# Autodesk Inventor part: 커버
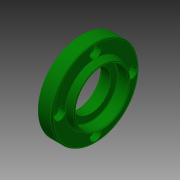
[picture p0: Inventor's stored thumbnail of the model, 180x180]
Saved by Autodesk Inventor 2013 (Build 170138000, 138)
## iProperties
Created: 2018-11
Part Number: 커버
Material: 알루미늄 6061
Document SubType Name: Modeling
Designer: mduedu
Density: 1 g/cm^3
Author: mduedu
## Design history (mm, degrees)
revolve "회전1" stored, may be unused: angle "d7" = 90 deg
sketch "스케치2"
  geometry: L1 (0, -20)-(0, 20) reference; L2 (0, 20)-(3, 20) reference; L3 (3, 20)-(3, 31) reference; L4 (3, 31)-(13, 31) reference; L5 (13, 31)-(13, 21.5) reference; L6 (18, 20)-(18, -20) reference; L7 (13, -21.5)-(13, -31) reference; L8 (13, -31)-(3, -31) reference; L9 (3, -31)-(3, -20) reference; L10 (3, -20)-(0, -20) reference; L11 (0, 0)-(3, 0); L12 (3, 0)-(3, 16.5); L13 (3, 16.5)-(0, 16.5); L14 (0, 16.5)-(0, 0); L15 (3, 0)-(9.7, 0); L16 (9.7, 0)-(9.7, 14); L17 (9.7, 14)-(3, 14); L18 (3, 14)-(3, 0); L19 (9.7, 0)-(18, 0); L20 (18, 0)-(18, 19); L21 (18, 19)-(9.7, 19); L22 (9.7, 19)-(9.7, 0); L23 (13, 21.5)-(18, 20) reference; L24 (18, -20)-(13, -21.5) reference
  constraints: 24 end point, 6 parallel, 3 horizontal, 3 perpendicular, 1 point on line
  dimensions: "d8" = 38 diameter of L21 L19; "d10" = 28 diameter of L17 L15; "d11" = 33 diameter of L13 L11; "d12" = 3 distance of L12.end L13.end; "d13" = 8.3 distance of L20.end L21.end
revolve "회전2" sketch "스케치2" stored, may be unused: angle "d14" = 90 deg
fillet "모깎기1" dims "d15" = 0.3
chamfer "모따기1" distance "d16" = 0.8; stored, may be unused: second distance "d17" = 2, angle "d18" = 30 deg
fillet "모깎기2" dims "d19" = 1
chamfer "모따기2" distance "d20" = 0.5; stored, may be unused: second distance "d21" = 2, angle "d22" = 30 deg
sketch "스케치3" dims "d23" = 52
  geometry: 6 further points
  constraints: 2 vertical alignment, 1 coincident, 7 other
  dimensions: "d26" = 360 deg dimension on point (0, 0) point (0, 26) (derived)
sketch "스케치4"
  geometry: C1 r 1.621 at (0, 25.5) reference; C2 r 1.621 at (25.5, 0) reference; C3 r 1.621 at (0, -25.5) reference; C4 r 1.621 at (-25.5, 0) reference
hole "구멍2" sketch "스케치4" at (0, 25.5), (25.5, 0), (0, -25.5), (-25.5, 0) diameter "d38" = 4.5; stored, may be unused: countersink angle "d42" = 90 deg, drill point angle "d44" = 118 deg; dims "d39" = 8, "d40" = 8, "d41" = 4.4, "d43" = 10
node "솔리드1"
sketch "스케치1"
  geometry: L1 (0, 0)-(3, 0); L2 (3, 0)-(3, 20); L3 (3, 20)-(0, 20); L4 (0, 20)-(0, 0); L5 (3, 0)-(13, 0); L6 (13, 0)-(13, 31); L7 (13, 31)-(3, 31); L8 (3, 31)-(3, 0); L9 (13, 0)-(18, 0); L10 (18, 0)-(18, 20); L11 (13, 15)-(13, 0); L12 (18, 20)-(13, 21.5)
  constraints: 24 end point, 5 parallel, 3 horizontal, 3 perpendicular, 1 point on line
  dimensions: "d0" = 62 diameter of L7 L5; "d3" = 40 diameter of L3 L1; "d4" = 3 distance of L2.end L3.end; "d5" = 10 distance of L6.end L7.end; "d6" = 18 distance between parallel lines of L10 L4; "d35" = 40 diameter of L10.end L9; "d37" = 43 diameter of L12.end L9
node "참조1"
node "참조2"
node "참조3"
node "참조4"
node "절단 모서리 투영1"
